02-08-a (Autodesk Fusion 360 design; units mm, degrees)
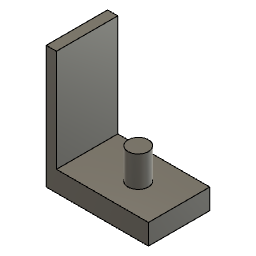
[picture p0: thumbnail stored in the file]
sketch "スケッチ1" plane through (0, 0, 0) normal (0, 1, 0) x axis (1, 0, 0)
  line L1 (50, 15) -> (0, 15)
  line L2 (50, -15) -> (50, 15)
  line L3 (0, -15) -> (50, -15)
  line L4 (0, 15) -> (0, -15)
  point P1 (0, 0)
  point P2 (0, 15)
  point P3 (50, 15)
  point P5 (0, -15)
  horizontal L1
  vertical L2
  horizontal L3
  vertical L4
  midpoint P1 L4
  dimension "d7" distance P2 P3 = 50
  dimension "d8" distance P2 P5 = 30
extrude "押し出し1" new body sketch "スケッチ1" along normal blind 10
sketch "スケッチ2" plane through (0, 10, 0) normal (0, 1, 0) x axis (-1, 0, 0)
  line L1 (-50, 15) -> (0, 15)
  line L2 (-50, -15) -> (-50, 15)
  line L3 (0, -15) -> (-50, -15)
  line L4 (0, 15) -> (0, -15)
  circle C1 centre (-30, 0) radius 5
  point P1 (0, 0)
  point P6 (-30, 0)
  horizontal P1 P6
  dimension "d9" diameter C1 = 10
  dimension "d10" distance P6 L4 = 30
extrude "押し出し2" add sketch "スケッチ2" profile of C1 along normal blind 15
sketch "スケッチ3" plane through (0, 10, 0) normal (0, 1, 0) x axis (-1, 0, 0)
  line L1 (-50, 15) -> (0, 15)
  line L2 (-50, -15) -> (-50, 15)
  line L3 (0, -15) -> (-50, -15)
  line L4 (0, 15) -> (0, -15)
  line L5 (-5, -15) -> (0, -15)
  line L6 (-5, 15) -> (-5, -15)
  line L7 (0, 15) -> (-5, 15)
  line L8 (0, -15) -> (0, 15)
  circle C1 centre (-30, 0) radius 5
  point P7 (0, -15)
  point P8 (-5, -15)
  horizontal L5
  vertical L6
  horizontal L7
  vertical L8
  collinear L3 L5
  collinear L4 L8
  collinear L1 L7
  dimension "d11" distance P7 P8 = 5
extrude "押し出し3" add sketch "スケッチ3" profile of L1 L3 L4 L5 L6 L7 L8 along normal blind 50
